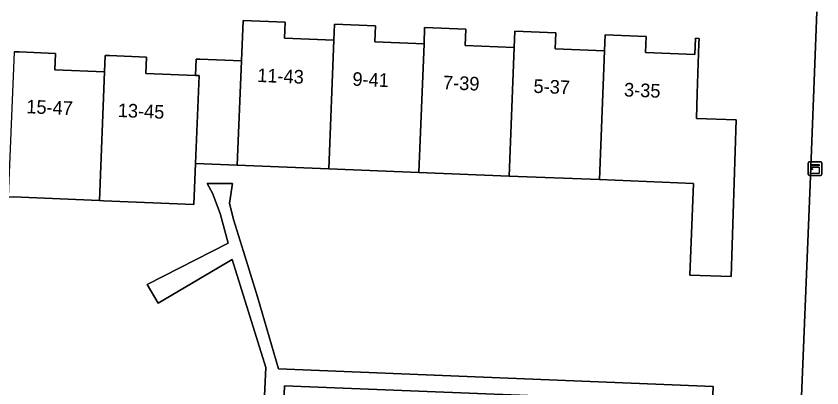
# Model space of a CAD drawing. Extents: x 161354 to 162026, y 386504 to 387460.
# Drawn here: x 161566.6 to 161625.8, y 387253 to 387280.3 of the extents above; entities that cross this region are included whole.
import ezdxf

# ---------------------------------------------------------------- set-up
doc = ezdxf.new("R2010")
doc.units = 0
for name, color, linetype in [('IMGEO_Erf', 7, 'Continuous'), ('IMGEO_Kast', 7, 'Continuous'), ('IMGEO_Pand', 7, 'Continuous'), ('IMGEO_Pand_nummerreeks', 7, 'Continuous'), ('IMGEO_Voetpad_open', 7, 'Continuous')]:
    doc.layers.add(name, color=color, linetype=linetype)

msp = doc.modelspace()

# ---------------------------------------------------------------- linework, layer by layer
at = {"layer": 'IMGEO_Erf'}
for points in [[(161623.487, 387231.32), (161623.903, 387241.645), (161624.246, 387250), (161624.983, 387267.974), (161625.457, 387280.654)], [(161566.467, 387277.727), (161566.83, 387277.712), (161569.505, 387277.604), (161569.457, 387276.405), (161573.104, 387276.256), (161573.152, 387277.455), (161573.47, 387277.442), (161576.199, 387277.332), (161576.151, 387276.133), (161579.798, 387275.984), (161579.846, 387277.183), (161580.115, 387277.172), (161583.165, 387277.048), (161583.288, 387280.025), (161586.386, 387279.898), (161586.34, 387278.709), (161589.97, 387278.566), (161590.017, 387279.755), (161593.018, 387279.637), (161592.972, 387278.448), (161596.59, 387278.306), (161596.636, 387279.495), (161599.66, 387279.376), (161599.614, 387278.187), (161603.222, 387278.045), (161603.268, 387279.234), (161606.282, 387279.115), (161606.236, 387277.926), (161609.855, 387277.784), (161609.902, 387278.973), (161612.924, 387278.853), (161612.878, 387277.664), (161616.496, 387277.522), (161616.542, 387278.711), (161616.809, 387278.7), (161616.796, 387278.335), (161616.67, 387274.667), (161616.607, 387272.828), (161619.544, 387272.716), (161619.172, 387261.212), (161616.138, 387261.311), (161616.392, 387268.053), (161609.481, 387268.326), (161602.846, 387268.588), (161596.216, 387268.851), (161589.596, 387269.112), (161582.847, 387269.379), (161579.806, 387269.503), (161579.684, 387266.496), (161573.037, 387266.778)], [(161550.176, 387252.756), (161584.82, 387251.403), (161584.961, 387254.538), (161582.48, 387262.469), (161577.049, 387259.255), (161576.237, 387260.627), (161582.187, 387263.651), (161581.615, 387265.851), (161581.048, 387267.337), (161580.643, 387268.039), (161582.505, 387268.039), (161582.293, 387266.598), (161582.579, 387265.409), (161583.313, 387263.061), (161584.354, 387259.724), (161585.906, 387254.436), (161617.831, 387253.127), (161617.782, 387251.931), (161586.329, 387253.184), (161585.49, 387231.146), (161616.871, 387229.793), (161622.343, 387229.58)], [(161573.037, 387266.778), (161572.73, 387266.791), (161566.397, 387267.059)]]:
    msp.add_lwpolyline(points, dxfattribs=at)
at = {"layer": 'IMGEO_Kast'}
for p, q in [((161624.833, 387268.716), (161624.833, 387269.557)), ((161624.833, 387269.557), (161624.833, 387268.716)), ((161624.908, 387269.641), (161625.749, 387269.641)), ((161625.749, 387269.641), (161624.908, 387269.641)), ((161625.833, 387269.566), (161625.833, 387268.725)), ((161625.833, 387268.725), (161625.833, 387269.566)), ((161625.758, 387268.641), (161624.917, 387268.641)), ((161624.917, 387268.641), (161625.758, 387268.641))]:
    msp.add_line(p, q, dxfattribs=at)
for points in [[(161625.028, 387269.431), (161625.628, 387269.431), (161625.628, 387269.346), (161625.028, 387269.346), (161625.028, 387269.431)], [(161625.028, 387269.256), (161625.628, 387269.256), (161625.628, 387268.767), (161625.028, 387268.767), (161625.028, 387269.256)]]:
    msp.add_lwpolyline(points, dxfattribs=at)
msp.add_circle((161625.112, 387269.105), 0.0377, dxfattribs=at)
for centre, start, end in [((161624.911, 387269.563), 92.4484, 184.28452), ((161624.911, 387269.563), 92.4484, 184.28452), ((161625.755, 387269.563), 2.4484, 94.28452), ((161625.755, 387269.563), 2.4484, 94.28452), ((161624.911, 387268.719), 182.4484, 274.28452), ((161624.911, 387268.719), 182.4484, 274.28452), ((161625.755, 387268.719), 272.4484, 4.28452), ((161625.755, 387268.719), 272.4484, 4.28452)]:
    msp.add_arc(centre, 0.0779, start, end, dxfattribs=at)
at = {"layer": 'IMGEO_Pand'}
for points in [[(161589.97, 387278.566), (161586.34, 387278.709), (161586.386, 387279.898), (161583.288, 387280.025), (161583.165, 387277.048), (161582.847, 387269.379), (161589.596, 387269.112)], [(161596.59, 387278.306), (161592.972, 387278.448), (161593.018, 387279.637), (161590.017, 387279.755), (161589.97, 387278.566), (161589.596, 387269.112), (161596.216, 387268.851)], [(161596.216, 387268.851), (161602.846, 387268.588), (161603.222, 387278.045), (161599.614, 387278.187), (161599.66, 387279.376), (161596.636, 387279.495), (161596.59, 387278.306)], [(161609.855, 387277.784), (161606.236, 387277.926), (161606.282, 387279.115), (161603.268, 387279.234), (161603.222, 387278.045), (161602.846, 387268.588), (161609.481, 387268.326)], [(161619.544, 387272.716), (161616.607, 387272.828), (161616.67, 387274.667), (161616.796, 387278.335), (161616.809, 387278.7), (161616.542, 387278.711), (161616.496, 387277.522), (161612.878, 387277.664), (161612.924, 387278.853), (161609.902, 387278.973), (161609.855, 387277.784), (161609.481, 387268.326), (161616.392, 387268.053), (161616.138, 387261.311), (161619.172, 387261.212)], [(161573.104, 387276.256), (161569.457, 387276.405), (161569.505, 387277.604), (161566.83, 387277.712), (161566.467, 387277.727), (161566.419, 387276.528), (161566.035, 387267.074), (161566.397, 387267.059), (161572.73, 387266.791)], [(161580.067, 387275.973), (161579.798, 387275.984), (161576.151, 387276.133), (161576.199, 387277.332), (161573.47, 387277.442), (161573.152, 387277.455), (161573.104, 387276.256), (161572.73, 387266.791), (161573.037, 387266.778), (161579.684, 387266.496), (161579.806, 387269.503)], [(161583.165, 387277.048), (161580.115, 387277.172), (161579.846, 387277.183), (161579.798, 387275.984), (161580.067, 387275.973), (161579.806, 387269.503), (161582.847, 387269.379)]]:
    msp.add_lwpolyline(points, close=True, dxfattribs=at)
at = {"layer": 'IMGEO_Voetpad_open'}
for points in [[(161625.457, 387280.654), (161624.983, 387267.974), (161624.246, 387250), (161623.903, 387241.645), (161623.487, 387231.32)], [(161551.639, 387251.577), (161584.786, 387250.371), (161583.994, 387231.211), (161585.49, 387231.146), (161586.329, 387253.184), (161617.782, 387251.931), (161617.831, 387253.127), (161585.906, 387254.436), (161584.354, 387259.724), (161583.313, 387263.061), (161582.579, 387265.409), (161582.293, 387266.598), (161582.505, 387268.039), (161580.643, 387268.039), (161581.048, 387267.337), (161581.615, 387265.851), (161582.187, 387263.651), (161576.237, 387260.627), (161577.049, 387259.255), (161582.48, 387262.469), (161584.961, 387254.538), (161584.82, 387251.403), (161550.176, 387252.756)]]:
    msp.add_lwpolyline(points, dxfattribs=at)

# ---------------------------------------------------------------- texts
at = {"layer": 'IMGEO_Pand_nummerreeks'}
for s, rotation, p in [('11-43', 357.74828, (161584.319, 387275.506)), ('9-41', 357.74828, (161591.316, 387275.23)), ('7-39', 357.74673, (161597.971, 387274.969)), ('5-37', 357.74828, (161604.623, 387274.706)), ('3-35', 357.74255, (161611.275, 387274.446)), ('15-47', 357.67379, (161567.345, 387273.207)), ('13-45', 357.67379, (161574.069, 387272.933))]:
    msp.add_text(s, height=1, rotation=rotation, dxfattribs=at).set_placement(p)

doc.saveas('drawing.dxf')
